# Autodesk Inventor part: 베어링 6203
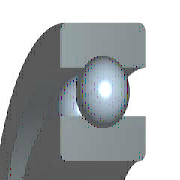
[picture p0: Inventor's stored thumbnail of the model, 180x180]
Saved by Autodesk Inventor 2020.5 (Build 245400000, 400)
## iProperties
IsCustomPart: 0
Created: 2016-04
Part Number: 베어링 6203
Material: 강철, 연강
Description: 깊은 그루브 볼 베어링
Document SubType Name: Modeling
Standard: KS B 2023
Designer: mdu
Standards Organization: KS
Language: ko-KR
Size Designation: 6203 - 17 x 40 x 12
Categories: <MemberInstance><Categories><Category DisplayName="샤프트 부품" InternalName="7f7aeb1f-a693-4053-b835-cee3144e0d98" Mnemonic="SHFT"><Category DisplayName="베어링" Inter
Density: 7.86 g/cm^3
Mass: 64.9809 g
Surface Area: 64.3582 cm^2
Volume: 8.26729 cm^3
Appearance: 노란색
Author: mdu
Revision Number: 1
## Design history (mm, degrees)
sketch "스케치" dims "d0" = 5.98 (= -0.26 x WD + 0.26 x BD)
  geometry: L1 (3.01, 14.25)-(8.99, 14.25); L2 (6, 14.25)-(6, 11.26); L3 (6, 14.25)-(6, 17.24); L4 (3.778, 12.249)-(0, 12.249); L5 (0, 8.5)-(12, 8.5); L6 (3.778, 16.251)-(0, 16.251); L7 (0, 20)-(12, 20); L8 (12, 8.5)-(12, 12.249); L9 (8.222, 12.249)-(12, 12.249); L10 (8.222, 16.251)-(12, 16.251); L11 (12, 20)-(12, 16.251); L12 (-1.4, 0)-(8.4, 0) reference; L13 (0, -0.3)-(0, 5.3) reference
  constraints: 22 end point, 4 point on line, 2 collinear, 2 perpendicular, 2 symmetric about line, 1 midpoint, 1 parallel, 14 other
  dimensions: "d9" = 17 diameter of L5 L12 (= WD); "d11" = 40 diameter of L7 L12 (= BD); "d12" = 12 distance between parallel lines of L8 L13 (= KB); "d13" = 24.498 diameter of L9 L12 (= 0.326 x BD + 0.674 x WD)
revolve "본체" stored, may be unused: angle "d6" = 90 deg
revolve "볼" stored, may be unused: angle "d7" = 90 deg
pattern_circular "IDS_ARRAYBALL[SIMPL:T]" dims angle "d3" = 360 deg
body "Solid1"
fillet "모깎기1" dims "d1" = 0.6 (= KRS)
other parameters: "WD" = 17 [user parameter; used in 5 equation terms], "BD" = 40 [user parameter; used in 5 equation terms], "KB" = 12 [user parameter; used in 1 equation term], "KRS" = 0.6 [user parameter; used in 1 equation term], "d4" = 0, "d5" = 0, "d8" = 0, "d14" = 0, "d15" = 0, "BBA" = 0 [user parameter], "BC0" = 4750000 [user parameter], "BC" = 9560000 [user parameter], "WR" = 8.5 (= 0.5 x WD) [user parameter]
